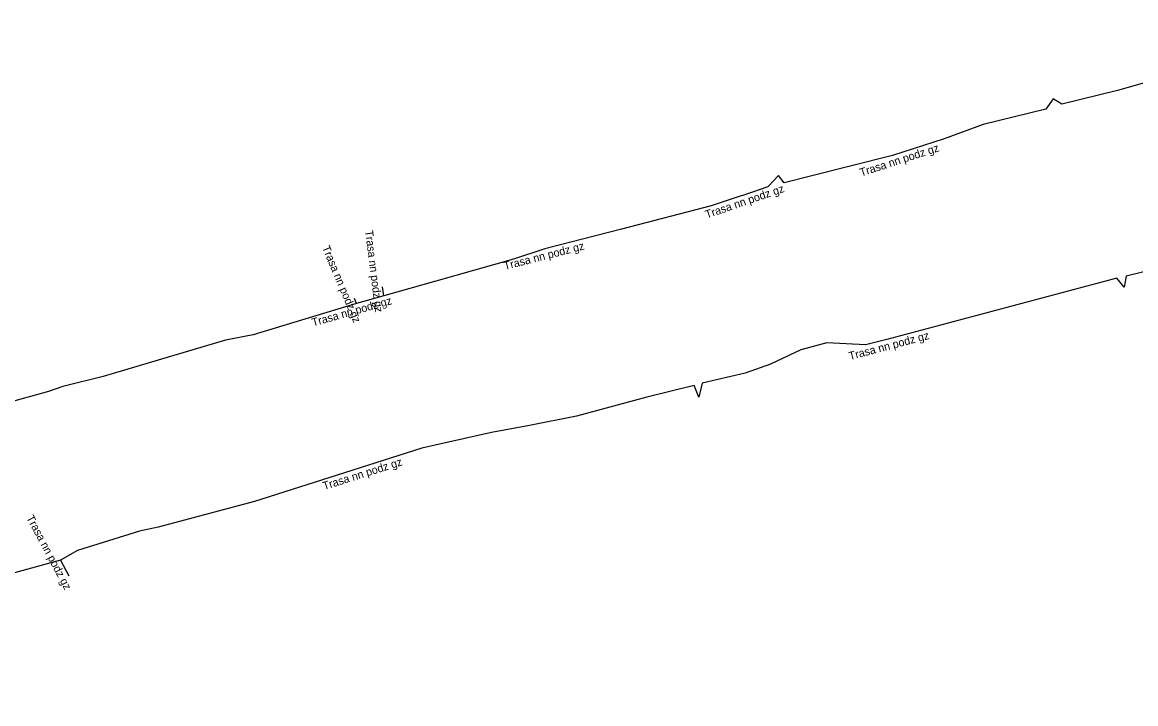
# Model space of a CAD drawing. Extents: x -690200 to -689130, y -975255 to -974631.
# Drawn here: x -690049.5 to -689979.9, y -975164.2 to -975121.6 of the extents above; entities that cross this region are included whole.
import ezdxf

# ---------------------------------------------------------------- set-up
doc = ezdxf.new("R2010")
doc.units = 0
doc.layers.add('Popiskový text - Ostatní atributy Trasy', color=7, linetype='Continuous')
doc.layers.add('Spojnice NN', color=7, linetype='Continuous')

msp = doc.modelspace()

# ---------------------------------------------------------------- linework, layer by layer
at = {"layer": 'Spojnice NN'}
for points in [[(-689965.53, -975121.62), (-689966.66, -975121.88), (-689970.12, -975122.63), (-689974.43, -975123.98), (-689981.07, -975125.89), (-689984.56, -975126.73), (-689985.1, -975126.41)], [(-689985.1, -975126.41), (-689985.55, -975127.06), (-689989.46, -975128), (-689991.91, -975128.9), (-689995.14, -975129.95), (-690000.25, -975131.24), (-690001.89, -975131.66), (-690002.25, -975131.2)], [(-690004.52, -975132.44), (-690002.89, -975131.88), (-690002.25, -975131.2)], [(-690004.52, -975132.44), (-690006.45, -975133.09), (-690012.06, -975134.55), (-690016.86, -975135.79), (-690018.82, -975136.42), (-690023.66, -975137.81), (-690026.92, -975138.71)], [(-689969.92, -975134.46), (-689970.85, -975134.91), (-689971.54, -975135.12), (-689976.87, -975136.59), (-689980.52, -975137.49), (-689980.66, -975138.17)], [(-689980.66, -975138.17), (-689981.11, -975137.62), (-689995.48, -975141.45), (-689996.81, -975141.77), (-689999.24, -975141.65), (-690000.86, -975142.09), (-690002.75, -975142.98), (-690004.34, -975143.55), (-690007.03, -975144.18), (-690007.24, -975145.05)], [(-690026.92, -975138.71), (-690028.61, -975139.19)], [(-690026.92, -975138.71), (-690026.99, -975138.15)], [(-690028.61, -975139.19), (-690035.08, -975141.16), (-690036.8, -975141.49), (-690044.44, -975143.76), (-690046.96, -975144.39), (-690047.86, -975144.7), (-690053.58, -975146.28), (-690057.91, -975147.41), (-690059.03, -975147.62), (-690063.73, -975148.97), (-690066.58, -975149.83), (-690069.36, -975150.66), (-690073.3, -975151.75), (-690073.83, -975151.88)], [(-690028.61, -975139.19), (-690028.74, -975138.88)], [(-690007.24, -975145.05), (-690007.53, -975144.32), (-690010.47, -975145.04), (-690014.87, -975146.23), (-690017.8, -975146.82), (-690020.18, -975147.25), (-690024.54, -975148.24), (-690029.36, -975149.77), (-690034.99, -975151.58), (-690041.02, -975153.17), (-690042.17, -975153.43), (-690046.05, -975154.63), (-690047.12, -975155.23)], [(-690047.12, -975155.23), (-690052.79, -975156.81), (-690066.57, -975160.81), (-690069.29, -975161.54), (-690074.92, -975163.6), (-690076.69, -975164.21)], [(-690047.12, -975155.23), (-690046.6, -975156.21)]]:
    msp.add_lwpolyline(points, dxfattribs=at)

# ---------------------------------------------------------------- texts
at = {"layer": 'Popiskový text - Ostatní atributy Trasy'}
for rotation, p in [(18.00817, (-689997.087, -975131.267)), (18.96058, (-690006.734, -975133.889)), (277.17538, (-690028.086, -975134.648)), (292.75098, (-690030.78, -975135.696)), (14.48473, (-690019.346, -975137.104)), (15.8558, (-690031.333, -975140.639)), (14.92397, (-689997.787, -975142.737)), (17.61086, (-690030.64, -975150.858)), (297.95097, (-690049.259, -975152.585))]:
    msp.add_text('Trasa nn podz gz', height=0.5, rotation=rotation, dxfattribs=at).set_placement(p)

doc.saveas('drawing.dxf')
